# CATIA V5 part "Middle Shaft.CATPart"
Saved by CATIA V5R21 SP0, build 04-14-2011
Part number: Middle shaft
Bounding box of the stored display mesh (mm): x 0 to 100, y -25 to 25, z -24.818 to 24.818
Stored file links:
  D:\CATIA V5R21 E-RESOURCES\CATIA-V5R21\catia-v5r21-Prts\c16_catia_v5r21_prt\Universal Joint-(Fig16-49)\Middle Shaft.CATPart
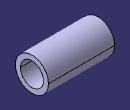
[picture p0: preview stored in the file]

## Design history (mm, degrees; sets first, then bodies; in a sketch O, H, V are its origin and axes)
Body1 (main body)
  Sketch1 on yz-plane, origin (0, 0, 0), H (0, 1, 0), V (0, 0, 1)
    circle A1 centre (0, 0) radius 25
    circle A2 centre (0, 0) radius 17.5
    radius A1 = 25
    radius A2 = 17.5
  Pad1: profile Sketch1, direction (1, 0, 0), length 100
